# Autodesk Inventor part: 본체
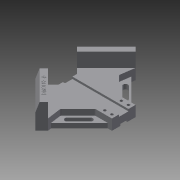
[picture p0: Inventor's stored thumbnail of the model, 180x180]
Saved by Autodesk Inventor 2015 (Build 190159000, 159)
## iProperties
Created: 2020-05
Part Number: 본체
Material: 일반
Document SubType Name: Modeling
Designer: now
Density: 1 g/cm^3
Appearance: 기본값
Author: now
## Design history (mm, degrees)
sketch "스케치2"
  geometry: L1 (-84.853, 0)-(0, 84.853); L2 (0, 84.853)-(84.853, 0); L3 (84.853, 0)-(0, -84.853); L4 (0, -84.853)-(-84.853, 0); L5 (64.853, -20)-(64.853, 20); L6 (-30.147, -16.005)-(-30.147, 16.005); L7 (-30.147, 16.005)-(-49.497, 35.355); L8 (-49.497, -35.355)-(-30.147, -16.005); 1 further point
  constraints: 16 end point, 5 parallel, 4 point on line, 1 perpendicular, 1 vertical, 1 vertical alignment
  dimensions: "d6" = 120 distance of L1.end L2.end; "d7" = 120 distance of L1.start L1.end; "d8" = 60 distance from line of point (0, 0) L4; "d9" = 60 distance from line of L3 point (0, 0); "d10" = 20 distance from line of L5 L2.end; "d11" = 95 distance between parallel lines of L5 L6; "d13" = 50 distance between parallel lines of L4 L7; "d14" = 50 distance between parallel lines of L1 L8
extrude "돌출1" new body sketch "스케치2" stored distance "d15" = 18; taper "d16" = 0 deg
sketch "스케치3"
  geometry: L1 (0, 84.853)-(-49.497, 35.355) reference; L2 (-49.497, 35.355)-(-30.147, 16.005) reference; L3 (-30.147, -16.005)-(-49.497, -35.355) reference; L4 (-49.497, -35.355)-(0, -84.853) reference; L5 (0, -84.853)-(64.853, -20) reference; L6 (64.853, 20)-(0, 84.853) reference; L7 (10.607, 74.246)-(-38.891, 24.749); L8 (-38.891, -24.749)-(10.607, -74.246); 1 further point
  constraints: 4 end point, 4 point on line, 2 parallel
  dimensions: "d17" = 15 distance between parallel lines of L4 L8; "d18" = 15 distance between parallel lines of L1 L7
extrude "돌출2" join sketch "스케치3" distance "d19" = 24; taper "d20" = 0 deg
sketch "스케치4"
  geometry: L1 (10.607, -74.246)-(64.853, -20) reference; L2 (64.853, -20)-(64.853, 20) reference; L3 (64.853, -20)-(36.569, -20); L4 (36.569, -20)-(7.071, -49.497); L5 (7.071, -49.497)-(10.607, -74.246); L6 (0, -84.853)-(10.607, -74.246) reference; L7 (-49.497, -35.355)-(0, -84.853) reference; L8 (9.723, -68.059)-(57.782, -20); 1 further point
  constraints: 8 end point, 3 point on line, 2 parallel, 1 horizontal
  dimensions: "d21" = 20 distance from line of point (0, 0) L3; "d23" = 30 distance from line of L7 L4.end; "d25" = 20 distance between parallel lines of L1 L4; "d26" = 5 distance between parallel lines of L1 L8
extrude "돌출3" cut sketch "스케치4" stored distance "d27" = 24; taper "d28" = 0 deg
extrude "돌출4" join sketch "스케치4" distance "d29" = 18; taper "d30" = 0 deg
extrude "돌출5" cut sketch "스케치4" distance "d31" = 10; taper "d32" = 0 deg
sketch "스케치5"
  geometry: L1 (57.782, -20)-(9.723, -68.059) reference; L2 (18.385, -49.497)-(38.184, -29.698); L3 (21.213, -52.326)-(41.012, -32.527); L4 (35.355, -26.87)-(15.556, -46.669); L5 (-49.497, -35.355)-(0, -84.853) reference; L6 (0, -84.853)-(10.607, -74.246) reference; A1 r 4 centre (18.385, -49.497) between (15.556, -46.669) and (21.213, -52.326); A2 r 4 centre (38.184, -29.698) between (41.012, -32.527) and (35.355, -26.87); 2 further points
  constraints: 8 end point, 4 point on circle, 4 tangent, 2 centre point, 2 parallel, 1 midpoint
  dimensions: "d33" = 8 distance between parallel lines of L3 L4; "d34" = 28 distance of L2.end L2.start; "d35" = 38 distance from line of L2.start L5; "d36" = 12 distance between parallel lines of L2 L6
extrude "돌출6" cut sketch "스케치5" stored distance "d37" = 10; taper "d38" = 0 deg
sketch "스케치6"
  geometry: L1 (0, 0)-(0, 40) reference; L2 (0, 12)-(3.5, 12); L3 (3.5, 12)-(3.5, 28); L4 (3.5, 28)-(0, 28); L5 (0, 28)-(0, 12); L6 (18, 3.995)-(18, 36.005) reference; L7 (18, 14)-(15, 14); L8 (15, 14)-(15, 26); L9 (15, 26)-(18, 26); L10 (18, 26)-(18, 14); 3 further points
  constraints: 16 end point, 4 parallel, 2 horizontal, 2 horizontal alignment, 2 midpoint, 2 perpendicular, 2 point on line
  dimensions: "d39" = 12 distance of L7.end L8.end; "d40" = 16 distance of L2.end L3.end; "d41" = 3 distance of L8.end L9.end; "d42" = 3.5 distance of L3.end L4.end
extrude "돌출7" cut sketch "스케치6" stored distance "d43" = 10; taper "d44" = 0 deg
sketch "스케치7"
  geometry: L1 (-64.853, -6)-(-64.853, -20) reference; L2 (-58.853, -14)-(-46.853, -14); 1 further point
  constraints: 2 end point, 1 horizontal
  dimensions: "d45" = 12 distance of L2.start L2.end; "d46" = 6 distance from line of L1 L2.start; "d47" = 14 distance from line of point (0, 0) L2
hole "구멍1" sketch "스케치7" at (-58.853, -14), (-46.853, -14) diameter "d48" = 4.5; stored, may be unused: countersink angle "d52" = 90 deg, drill point angle "d54" = 118 deg; dims "d49" = 6, "d50" = 8, "d51" = 10, "d53" = 8
fillet "모깎기1" dims "d55" = 3
sketch "스케치8"
  geometry: L1 (0, 0)-(-15, 0) reference; L2 (0, 42)-(0, 0) reference; L3 (0, 15)-(-5, 0); 1 further point
  constraints: 2 end point, 2 point on line
  dimensions: "d56" = 5 distance from line of L2 L3.end; "d57" = 15 distance from line of L3.start L1
extrude "돌출8" cut sketch "스케치8" stored distance "d58" = 10; taper "d59" = 0 deg
sketch "스케치9"
  geometry: L1 (10.607, -74.246)-(-38.891, -24.749) reference; L2 (-38.891, -24.749)-(-45.962, -31.82) reference; 2 further points
  constraints: 1 other
  dimensions: "d60" = 35 distance from line of point (-17.678, -53.033) L2; "d61" = 5 distance from line of L1 point (-17.678, -53.033)
feature "엠보싱1" sketch "스케치9" dims "d6" = 120, "d7" = 120, "d8" = 60, "d9" = 60, "d10" = 20, "d11" = 95, "d13" = 50, "d14" = 50, "d17" = 15, "d62" = 0.5, "d63" = 0
node "솔리드1"
mirror "대칭1"
mirror "대칭2"
mirror "대칭3"
